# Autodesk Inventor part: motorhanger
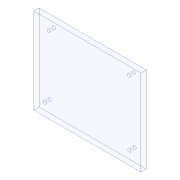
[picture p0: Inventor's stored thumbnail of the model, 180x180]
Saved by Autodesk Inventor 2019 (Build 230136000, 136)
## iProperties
Created: 2019-10
Part Number: motorhanger
Material: Water
Document SubType Name: Modeling
Designer: hp
Density: 0.9983 g/cm^3
Appearance: Tropical Blue
Author: hp
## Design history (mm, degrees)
sketch "Sketch1"
  geometry: L1 (-32.586, 11.408)-(67.414, 11.408); L2 (67.414, 11.408)-(67.414, -68.592); L3 (67.414, -68.592)-(-32.586, -68.592); L4 (-32.586, -68.592)-(-32.586, 11.408); 1 further point
  constraints: 8 end point, 2 parallel, 1 horizontal, 1 perpendicular
  dimensions: "d4" = 100 distance of L2.end L3.end; "d5" = 80 distance of L1.end L2.end
extrude "Extrusion1" new body sketch "Sketch1" distance "d2" = 5; taper "d3" = 0 deg
sketch "Sketch2"
  geometry: 2 further points
hole "Hole1" sketch "Sketch2" at (-18.711, 2.394) diameter "d6" = 3; stored, may be unused: countersink angle "d10" = 90 deg, drill point angle "d12" = 0 deg; dims "d7" = 6, "d8" = 4, "d9" = 2, "d11" = 12
sketch "Sketch3"
  geometry: 4 further points
hole "Hole2" sketch "Sketch3" at (56.006, 3.743), (-22.299, -57.161), (56.639, -56.443) diameter "d13" = 3; stored, may be unused: countersink angle "d17" = 90 deg, drill point angle "d19" = 0 deg; dims "d14" = 6, "d15" = 4, "d16" = 2, "d18" = 12
body "Solid1"
